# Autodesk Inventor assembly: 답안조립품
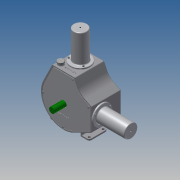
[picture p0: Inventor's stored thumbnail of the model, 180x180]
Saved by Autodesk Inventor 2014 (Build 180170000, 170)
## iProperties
Created: 2017-05
Part Number: 답안조립품
Document SubType Name: Assembly
Designer: 702-11
Author: 702-11
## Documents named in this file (13)
- C:\Users\702-11\Desktop\370508V1007\답안조립품.iam
- C:\Users\702-11\Desktop\370508V1007\본체.ipt
- C:\Users\702-11\Desktop\370508V1007\너트 M3.ipt
- C:\Users\702-11\Desktop\370508V1007\베어링 20 x 37 x 9.ipt
- C:\Users\702-11\Desktop\370508V1007\볼트 M3 x 12.ipt
- C:\Users\702-11\Desktop\370508V1007\실린더.ipt
- C:\Users\702-11\Desktop\370508V1007\앞커버.ipt
- C:\Users\702-11\Desktop\370508V1007\축.ipt
- C:\Users\702-11\Desktop\370508V1007\측정게이지.ipt
- C:\Users\702-11\Desktop\370508V1007\커넥팅로드 캡.ipt
- C:\Users\702-11\Desktop\370508V1007\커넥팅로드.ipt
- C:\Users\702-11\Desktop\370508V1007\피스톤 핀.ipt
- C:\Users\702-11\Desktop\370508V1007\피스톤.ipt
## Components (4 placed, 2 different names)
1. 피스톤 핀:1
2. 피스톤:1
3. 피스톤 핀:2
4. 피스톤:2
